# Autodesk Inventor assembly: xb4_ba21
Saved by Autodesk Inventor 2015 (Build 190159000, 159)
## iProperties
Created: 2018-04
Part Number: xb4_ba21
Checked By: TraceParts S.A.
Catalog Web Link: www.traceparts.com
Document SubType Name: Assembly
Designer: TraceParts
Company: TraceParts S.A.
Author: TraceParts
REFERENCE: XB4 BA21
DESIGN: Unité de commande et de signalisation Ø 22 Harmony XB4 métallique - Bouton poussoir à impulsion sans marquage à poussoir affleurant - Produit complet, XB4 BA21
SUPPLIER: Schneider Electric
TraceParts.PartNumber: 10-24042009-067390
TraceParts.PartTitle: Unité de commande et de signalisation Ø 22 Harmony XB4 métallique - Bouton poussoir à impulsion sans marquage à poussoir affleurant - Produit complet
TraceParts.InstanceId: 10-24042009-067390A0109BZG8AHJ1XWD1O8ISI8IX
TraceParts.PartStatus: Published
TraceParts.PartVersion: 1.1.4
TRACEPARTS: TRACEPARTS
TraceParts.PartLanguage: fr
TraceParts.ClassPath: SCHNEIDER_ELECTRIC:/F_SCHNEIDER/F_TELEMECANIQUE/F_TELEMECANIQUE.04/F_TELEMECANIQUE.04.010/F_TELEMECANIQUE.04.010.010/10-24042009-067390
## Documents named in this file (6)
- C:\TPO v2\SharedFS\Outgoing\xb4_ba21.iam
- C:\TPO v2\SharedFS\Outgoing\xb4_ba21_01.ipt
- C:\TPO v2\SharedFS\Outgoing\xb4_ba21_02.ipt
- C:\TPO v2\SharedFS\Outgoing\xb4_ba21_03.ipt
- C:\TPO v2\SharedFS\Outgoing\xb4_ba21_04.ipt
- C:\TPO v2\SharedFS\Outgoing\xb4_ba21_05.ipt
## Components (5 placed, 5 different names)
1. xb4_ba21_01:1
2. xb4_ba21_02:1
3. xb4_ba21_03:1
4. xb4_ba21_04:1
5. xb4_ba21_05:1
